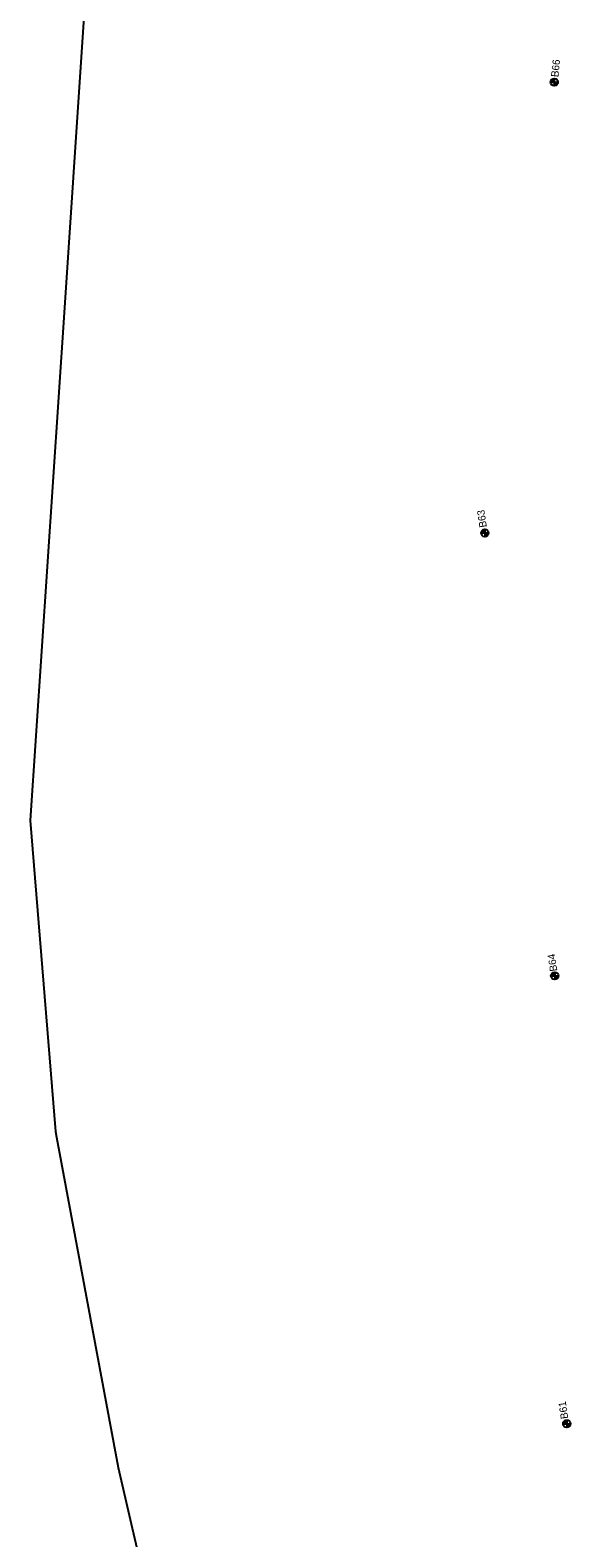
# Model space of a CAD drawing. Extents: x 311409 to 379449, y 121539 to 224848.
# Drawn here: x 358737 to 359468, y 163905 to 165933 of the extents above; entities that cross this region are included whole.
import ezdxf

# ---------------------------------------------------------------- set-up
doc = ezdxf.new("R2010")
doc.units = 0
for name, color, linetype in [('E_SOIL_BORE1 [KAPUR_CADDS_LEVELS]', 7, 'Continuous'), ('E_SOIL_BORE2 [KAPUR_CADDS_LEVELS]', 7, 'Continuous'), ('P_MARK', 7, 'Continuous'), ('P_TC', 7, 'Continuous')]:
    doc.layers.add(name, color=color, linetype=linetype)

msp = doc.modelspace()

# ---------------------------------------------------------------- linework, layer by layer
at = {"layer": 'P_MARK'}
for p, q in [((359437.8, 165863.3), (359447.8, 165863.3)), ((359442.8, 165868.3), (359442.8, 165858.3)), ((359344.2, 165256.8), (359354.2, 165256.8)), ((359349.2, 165261.8), (359349.2, 165251.8)), ((359438.4, 164660.9), (359448.4, 164660.9)), ((359443.4, 164665.9), (359443.4, 164655.9)), ((359454.6, 164058.3), (359464.6, 164058.3)), ((359459.6, 164063.3), (359459.6, 164053.3))]:
    msp.add_line(p, q, dxfattribs=at)
for centre in [(359442.8, 165863.3), (359349.2, 165256.8), (359443.4, 164660.9), (359459.6, 164058.3)]:
    msp.add_circle(centre, 5, dxfattribs=at)
for centre, radius, start, end in [((359442.8, 165863.3), 4.5, 89.9869, 179.9869), ((359442.8, 165863.3), 4, 89.9869, 179.9869), ((359442.8, 165863.3), 3.5, 89.9869, 179.9869), ((359442.8, 165863.3), 3, 89.9869, 179.9869), ((359442.8, 165863.3), 2.5, 89.9869, 179.9869), ((359442.8, 165863.3), 2, 89.9869, 179.9869), ((359442.8, 165863.3), 1.5, 89.9869, 179.9869), ((359442.8, 165863.3), 1, 89.9869, 179.9869), ((359442.8, 165863.3), 0.5, 89.9869, 179.9869), ((359442.8, 165863.3), 4.5, 269.9869, 359.9869), ((359442.8, 165863.3), 4, 269.9869, 359.9869), ((359442.8, 165863.3), 3.5, 269.9869, 359.9869), ((359442.8, 165863.3), 3, 269.9869, 359.9869), ((359442.8, 165863.3), 2.5, 269.9869, 359.9869), ((359442.8, 165863.3), 2, 269.9869, 359.9869), ((359442.8, 165863.3), 1.5, 269.9869, 359.9869), ((359442.8, 165863.3), 1, 269.9869, 359.9869), ((359442.8, 165863.3), 0.5, 269.9869, 359.9869), ((359349.2, 165256.8), 4.5, 89.9869, 179.9869), ((359349.2, 165256.8), 4, 89.9869, 179.9869), ((359349.2, 165256.8), 3.5, 89.9869, 179.9869), ((359349.2, 165256.8), 3, 89.9869, 179.9869), ((359349.2, 165256.8), 2.5, 89.9869, 179.9869), ((359349.2, 165256.8), 2, 89.9869, 179.9869), ((359349.2, 165256.8), 1.5, 89.9869, 179.9869), ((359349.2, 165256.8), 1, 89.9869, 179.9869), ((359349.2, 165256.8), 0.5, 89.9869, 179.9869), ((359349.2, 165256.8), 4.5, 269.9869, 359.9869), ((359349.2, 165256.8), 4, 269.9869, 359.9869), ((359349.2, 165256.8), 3.5, 269.9869, 359.9869), ((359349.2, 165256.8), 3, 269.9869, 359.9869), ((359349.2, 165256.8), 2.5, 269.9869, 359.9869), ((359349.2, 165256.8), 2, 269.9869, 359.9869), ((359349.2, 165256.8), 1.5, 269.9869, 359.9869), ((359349.2, 165256.8), 1, 269.9869, 359.9869), ((359349.2, 165256.8), 0.5, 269.9869, 359.9869), ((359443.4, 164660.9), 4.5, 89.9869, 179.9869), ((359443.4, 164660.9), 4, 89.9869, 179.9869), ((359443.4, 164660.9), 3.5, 89.9869, 179.9869), ((359443.4, 164660.9), 3, 89.9869, 179.9869), ((359443.4, 164660.9), 2.5, 89.9869, 179.9869), ((359443.4, 164660.9), 2, 89.9869, 179.9869), ((359443.4, 164660.9), 1.5, 89.9869, 179.9869), ((359443.4, 164660.9), 1, 89.9869, 179.9869), ((359443.4, 164660.9), 0.5, 89.9869, 179.9869), ((359443.4, 164660.9), 4.5, 269.9869, 359.9869), ((359443.4, 164660.9), 4, 269.9869, 359.9869), ((359443.4, 164660.9), 3.5, 269.9869, 359.9869), ((359443.4, 164660.9), 3, 269.9869, 359.9869), ((359443.4, 164660.9), 2.5, 269.9869, 359.9869), ((359443.4, 164660.9), 2, 269.9869, 359.9869), ((359443.4, 164660.9), 1.5, 269.9869, 359.9869), ((359443.4, 164660.9), 1, 269.9869, 359.9869), ((359443.4, 164660.9), 0.5, 269.9869, 359.9869), ((359459.6, 164058.3), 4.5, 89.9869, 179.9869), ((359459.6, 164058.3), 4, 89.9869, 179.9869), ((359459.6, 164058.3), 3.5, 89.9869, 179.9869), ((359459.6, 164058.3), 3, 89.9869, 179.9869), ((359459.6, 164058.3), 2.5, 89.9869, 179.9869), ((359459.6, 164058.3), 2, 89.9869, 179.9869), ((359459.6, 164058.3), 1.5, 89.9869, 179.9869), ((359459.6, 164058.3), 1, 89.9869, 179.9869), ((359459.6, 164058.3), 0.5, 89.9869, 179.9869), ((359459.6, 164058.3), 4.5, 269.9869, 359.9869), ((359459.6, 164058.3), 4, 269.9869, 359.9869), ((359459.6, 164058.3), 3.5, 269.9869, 359.9869), ((359459.6, 164058.3), 3, 269.9869, 359.9869), ((359459.6, 164058.3), 2.5, 269.9869, 359.9869), ((359459.6, 164058.3), 2, 269.9869, 359.9869), ((359459.6, 164058.3), 1.5, 269.9869, 359.9869), ((359459.6, 164058.3), 1, 269.9869, 359.9869), ((359459.6, 164058.3), 0.5, 269.9869, 359.9869)]:
    msp.add_arc(centre, radius, start, end, dxfattribs=at)
at = {"layer": 'P_TC'}
for p, q in [((358772.3, 164443.9), (358855.3, 163999.4)), ((358855.3, 163999.4), (358874.4, 163917.9))]:
    msp.add_line(p, q, dxfattribs=at)
for points in [[(359467.9, 174515.5), (359203.4, 171166.2), (359130.1, 170237.2), (358905.5, 167392.6), (358782.9, 165553.3), (358736.9, 164870), (358770.9, 164451.4), (358772.3, 164443.9)], [(358874.4, 163917.9), (359033, 163240.2)]]:
    msp.add_lwpolyline(points, dxfattribs=at)

# ---------------------------------------------------------------- texts
at = {"layer": 'E_SOIL_BORE1 [KAPUR_CADDS_LEVELS]'}
for s, p in [('B63', (359352.1, 165264.9)), ('B64', (359447, 164667.6))]:
    msp.add_text(s, height=10, rotation=98.5151, dxfattribs=at).set_placement(p)
at = {"layer": 'E_SOIL_BORE2 [KAPUR_CADDS_LEVELS]'}
for s, rotation, p in [('B66', 84.1728, (359448.3, 165869.7)), ('B61', 98.5151, (359461.7, 164065.5))]:
    msp.add_text(s, height=10, rotation=rotation, dxfattribs=at).set_placement(p)

doc.saveas('drawing.dxf')
